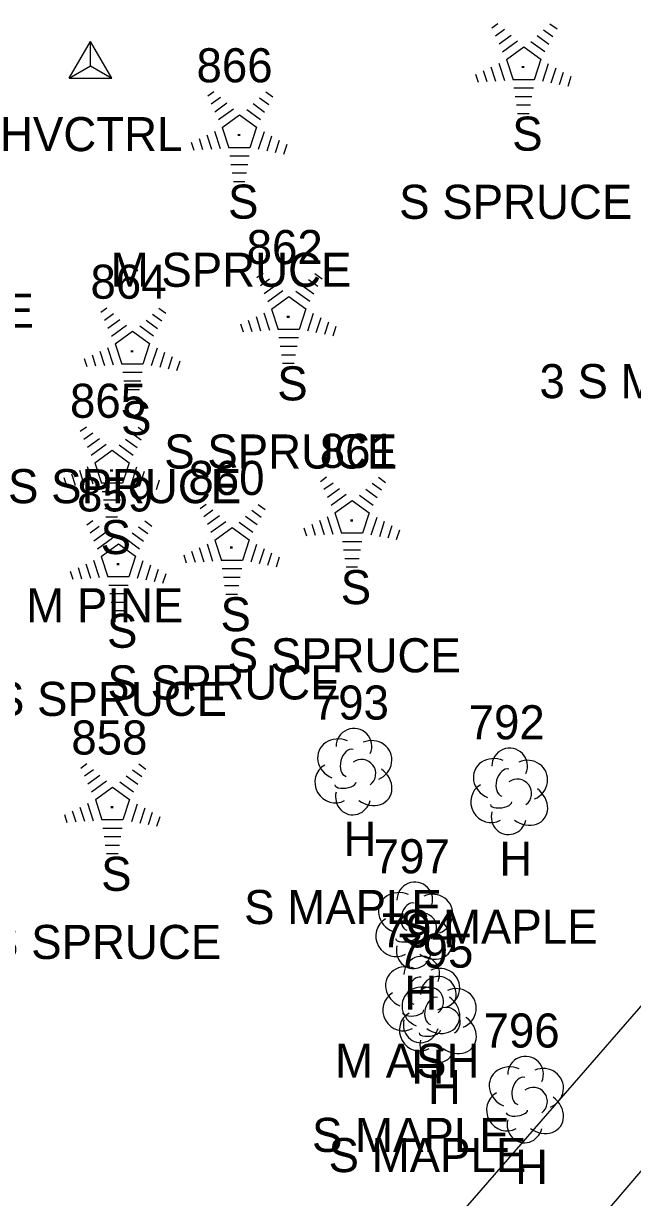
# Model space of a CAD drawing. Extents: x 1545627 to 1546562, y 571176 to 576667.
# Drawn here: x 1546211.1 to 1546246.9, y 572339.9 to 572408.8 of the extents above; entities that cross this region are included whole.
import ezdxf

# ---------------------------------------------------------------- set-up
doc = ezdxf.new("R2010")
doc.units = 0
for name, color, linetype in [('C_A', 7, 'Continuous'), ('CPSM', 7, 'Continuous'), ('L_A', 7, 'Continuous'), ('L_C', 7, 'Continuous'), ('L_I', 7, 'Continuous'), ('LAWE', 7, 'Continuous'), ('LELB', 7, 'Continuous'), ('LTC', 7, 'Continuous'), ('LTD', 7, 'Continuous')]:
    doc.layers.add(name, color=color, linetype=linetype)

msp = doc.modelspace()

# ---------------------------------------------------------------- linework, layer by layer
at = {"layer": 'CPSM'}
for p, q in [((1546213.82, 572405.561), (1546215.07, 572407.726)), ((1546216.32, 572405.561), (1546215.07, 572407.726)), ((1546215.07, 572406.282), (1546215.07, 572407.726)), ((1546213.82, 572405.561), (1546215.07, 572406.282)), ((1546215.07, 572406.282), (1546215.07, 572406.282)), ((1546215.07, 572406.282), (1546216.32, 572405.561)), ((1546213.82, 572405.561), (1546216.32, 572405.561))]:
    msp.add_line(p, q, dxfattribs=at)
at = {"layer": 'LAWE'}
msp.add_lwpolyline([(1546079.438, 571966.947), (1546077.788, 571985.488), (1546075.176, 572034.738), (1546072.514, 572073.367), (1546072.957, 572091.545), (1546079.326, 572109.636), (1546089.965, 572133.875), (1546098.205, 572146.168), (1546103.269, 572146.803), (1546106.386, 572149.622), (1546130.143, 572181.263), (1546136.759, 572192.153), (1546140.729, 572200.768), (1546161.621, 572243.317), (1546187.565, 572282.786), (1546232.645, 572334.154), (1546255.297, 572360.235), (1546268.959, 572391.116)], dxfattribs=at)
at = {"layer": 'LELB'}
msp.add_lwpolyline([(1546140.457, 572188.687), (1546144.086, 572197.302), (1546164.869, 572240.482), (1546191.763, 572281.913), (1546238.283, 572330.782), (1546258.38, 572354.309), (1546270.264, 572391.299)], dxfattribs=at)
at = {"layer": 'LTC'}
for p, q in [((1546238.614, 572408.517), (1546238.969, 572408.774)), ((1546242.013, 572408.757), (1546242.432, 572408.453)), ((1546238.824, 572408.051), (1546239.353, 572408.435)), ((1546239.033, 572407.585), (1546239.737, 572408.097)), ((1546241.27, 572408.06), (1546241.95, 572407.567)), ((1546241.641, 572408.409), (1546242.191, 572408.01)), ((1546239.243, 572407.12), (1546240.121, 572407.758)), ((1546239.468, 572406.665), (1546240.479, 572407.399)), ((1546240.479, 572407.399), (1546241.476, 572406.674)), ((1546240.899, 572407.712), (1546241.709, 572407.123)), ((1546239.468, 572406.665), (1546239.855, 572405.471)), ((1546241.476, 572406.674), (1546241.085, 572405.471)), ((1546238.102, 572406.013), (1546238.314, 572405.361)), ((1546238.558, 572406.229), (1546238.829, 572405.394)), ((1546239.013, 572406.445), (1546239.344, 572405.426)), ((1546241.914, 572406.403), (1546241.576, 572405.364)), ((1546242.358, 572406.153), (1546242.071, 572405.268)), ((1546237.647, 572405.796), (1546237.799, 572405.328)), ((1546241.085, 572405.471), (1546239.855, 572405.471)), ((1546242.803, 572405.903), (1546242.566, 572405.173)), ((1546243.247, 572405.653), (1546243.06, 572405.078)), ((1546221.948, 572404.528), (1546222.303, 572404.785)), ((1546225.347, 572404.768), (1546225.766, 572404.464)), ((1546241.047, 572404.971), (1546239.902, 572404.971)), ((1546222.158, 572404.062), (1546222.687, 572404.447)), ((1546222.368, 572403.597), (1546223.071, 572404.108)), ((1546224.605, 572404.072), (1546225.284, 572403.578)), ((1546224.975, 572404.42), (1546225.525, 572404.021)), ((1546240.963, 572404.471), (1546239.975, 572404.471)), ((1546240.879, 572403.971), (1546240.048, 572403.971)), ((1546222.577, 572403.131), (1546223.455, 572403.769)), ((1546222.802, 572402.676), (1546223.813, 572403.41)), ((1546223.813, 572403.41), (1546224.81, 572402.685)), ((1546224.233, 572403.723), (1546225.043, 572403.134)), ((1546240.795, 572403.471), (1546240.12, 572403.471)), ((1546222.802, 572402.676), (1546223.189, 572401.482)), ((1546224.81, 572402.685), (1546224.419, 572401.482)), ((1546221.436, 572402.024), (1546221.648, 572401.372)), ((1546221.892, 572402.24), (1546222.163, 572401.405)), ((1546222.347, 572402.457), (1546222.678, 572401.437)), ((1546225.248, 572402.414), (1546224.91, 572401.375)), ((1546225.693, 572402.164), (1546225.405, 572401.279)), ((1546226.137, 572401.914), (1546225.9, 572401.184)), ((1546220.981, 572401.807), (1546221.133, 572401.339)), ((1546224.419, 572401.482), (1546223.189, 572401.482)), ((1546226.581, 572401.664), (1546226.395, 572401.089)), ((1546224.381, 572400.982), (1546223.236, 572400.982)), ((1546224.297, 572400.482), (1546223.309, 572400.482)), ((1546224.213, 572399.982), (1546223.382, 572399.982)), ((1546224.13, 572399.482), (1546223.455, 572399.482)), ((1546224.835, 572393.862), (1546225.189, 572394.12)), ((1546225.044, 572393.397), (1546225.573, 572393.781)), ((1546227.862, 572393.755), (1546228.411, 572393.355)), ((1546228.233, 572394.103), (1546228.652, 572393.798)), ((1546225.254, 572392.931), (1546225.957, 572393.442)), ((1546225.463, 572392.465), (1546226.342, 572393.103)), ((1546227.12, 572393.058), (1546227.929, 572392.469)), ((1546227.491, 572393.406), (1546228.17, 572392.912)), ((1546225.688, 572392.01), (1546226.7, 572392.745)), ((1546226.7, 572392.745), (1546227.697, 572392.02)), ((1546215.673, 572391.829), (1546216.028, 572392.086)), ((1546215.883, 572391.363), (1546216.412, 572391.747)), ((1546218.7, 572391.721), (1546219.25, 572391.322)), ((1546219.071, 572392.069), (1546219.491, 572391.765)), ((1546224.778, 572391.575), (1546225.049, 572390.74)), ((1546225.233, 572391.791), (1546225.564, 572390.772)), ((1546225.688, 572392.01), (1546226.075, 572390.817)), ((1546227.697, 572392.02), (1546227.305, 572390.817)), ((1546228.134, 572391.749), (1546227.796, 572390.71)), ((1546228.579, 572391.499), (1546228.291, 572390.614)), ((1546216.092, 572390.897), (1546216.796, 572391.409)), ((1546216.302, 572390.432), (1546217.18, 572391.07)), ((1546217.958, 572391.024), (1546218.768, 572390.435)), ((1546218.329, 572391.372), (1546219.009, 572390.879)), ((1546223.867, 572391.142), (1546224.019, 572390.674)), ((1546224.322, 572391.358), (1546224.534, 572390.707)), ((1546227.305, 572390.817), (1546226.075, 572390.817)), ((1546229.023, 572391.249), (1546228.786, 572390.519)), ((1546229.467, 572390.998), (1546229.281, 572390.424)), ((1546216.527, 572389.977), (1546217.538, 572390.711)), ((1546217.538, 572390.711), (1546218.535, 572389.986)), ((1546227.267, 572390.317), (1546226.122, 572390.317)), ((1546215.617, 572389.541), (1546215.888, 572388.706)), ((1546216.072, 572389.757), (1546216.403, 572388.738)), ((1546216.527, 572389.977), (1546216.914, 572388.783)), ((1546218.535, 572389.986), (1546218.144, 572388.783)), ((1546218.973, 572389.715), (1546218.635, 572388.676)), ((1546219.417, 572389.465), (1546219.13, 572388.58)), ((1546227.183, 572389.817), (1546226.195, 572389.817)), ((1546214.706, 572389.108), (1546214.858, 572388.64)), ((1546215.161, 572389.325), (1546215.373, 572388.673)), ((1546218.144, 572388.783), (1546216.914, 572388.783)), ((1546219.862, 572389.215), (1546219.625, 572388.485)), ((1546220.306, 572388.965), (1546220.119, 572388.39)), ((1546227.1, 572389.317), (1546226.268, 572389.317)), ((1546227.016, 572388.817), (1546226.341, 572388.817)), ((1546218.106, 572388.283), (1546216.961, 572388.283)), ((1546218.022, 572387.783), (1546217.034, 572387.783)), ((1546217.938, 572387.283), (1546217.106, 572387.283)), ((1546217.854, 572386.783), (1546217.179, 572386.783)), ((1546214.473, 572384.841), (1546214.828, 572385.099)), ((1546214.683, 572384.376), (1546215.212, 572384.76)), ((1546217.501, 572384.733), (1546218.05, 572384.334)), ((1546217.872, 572385.082), (1546218.291, 572384.777)), ((1546214.893, 572383.91), (1546215.596, 572384.421)), ((1546215.102, 572383.444), (1546215.981, 572384.082)), ((1546216.758, 572384.037), (1546217.568, 572383.448)), ((1546217.13, 572384.385), (1546217.809, 572383.891)), ((1546215.327, 572382.989), (1546216.338, 572383.724)), ((1546216.338, 572383.724), (1546217.336, 572382.999)), ((1546214.417, 572382.554), (1546214.688, 572381.718)), ((1546214.872, 572382.77), (1546215.203, 572381.751)), ((1546215.327, 572382.989), (1546215.714, 572381.796)), ((1546217.336, 572382.999), (1546216.944, 572381.796)), ((1546217.773, 572382.728), (1546217.435, 572381.688)), ((1546213.506, 572382.12), (1546213.658, 572381.653)), ((1546213.961, 572382.337), (1546214.173, 572381.685)), ((1546218.218, 572382.478), (1546217.93, 572381.593)), ((1546218.662, 572382.228), (1546218.425, 572381.498)), ((1546219.106, 572381.977), (1546218.92, 572381.403)), ((1546228.556, 572381.903), (1546228.911, 572382.161)), ((1546231.955, 572382.144), (1546232.374, 572381.839)), ((1546216.944, 572381.796), (1546215.714, 572381.796)), ((1546216.906, 572381.296), (1546215.761, 572381.296)), ((1546228.766, 572381.438), (1546229.295, 572381.822)), ((1546228.975, 572380.972), (1546229.679, 572381.483)), ((1546231.213, 572381.447), (1546231.892, 572380.953)), ((1546231.583, 572381.795), (1546232.133, 572381.396)), ((1546216.822, 572380.796), (1546215.834, 572380.796)), ((1546221.506, 572380.312), (1546221.86, 572380.569)), ((1546224.904, 572380.552), (1546225.323, 572380.248)), ((1546229.185, 572380.506), (1546230.063, 572381.144)), ((1546229.41, 572380.051), (1546230.421, 572380.786)), ((1546230.421, 572380.786), (1546231.418, 572380.061)), ((1546230.841, 572381.099), (1546231.651, 572380.51)), ((1546216.738, 572380.296), (1546215.907, 572380.296)), ((1546216.655, 572379.796), (1546215.98, 572379.796)), ((1546221.715, 572379.846), (1546222.245, 572380.231)), ((1546221.925, 572379.381), (1546222.629, 572379.892)), ((1546224.162, 572379.856), (1546224.841, 572379.362)), ((1546224.533, 572380.204), (1546225.082, 572379.805)), ((1546228.955, 572379.832), (1546229.286, 572378.813)), ((1546229.41, 572380.051), (1546229.797, 572378.858)), ((1546231.418, 572380.061), (1546231.027, 572378.858)), ((1546231.856, 572379.79), (1546231.518, 572378.75)), ((1546214.851, 572379.345), (1546215.205, 572379.603)), ((1546215.06, 572378.88), (1546215.589, 572379.264)), ((1546217.878, 572379.238), (1546218.427, 572378.838)), ((1546218.249, 572379.586), (1546218.668, 572379.281)), ((1546222.135, 572378.915), (1546223.013, 572379.553)), ((1546222.359, 572378.46), (1546223.371, 572379.194)), ((1546223.371, 572379.194), (1546224.368, 572378.469)), ((1546223.791, 572379.507), (1546224.6, 572378.918)), ((1546227.589, 572379.182), (1546227.741, 572378.715)), ((1546228.044, 572379.399), (1546228.256, 572378.747)), ((1546228.5, 572379.616), (1546228.771, 572378.78)), ((1546232.3, 572379.54), (1546232.013, 572378.655)), ((1546232.745, 572379.29), (1546232.508, 572378.56)), ((1546215.27, 572378.414), (1546215.974, 572378.925)), ((1546215.479, 572377.948), (1546216.358, 572378.586)), ((1546217.136, 572378.541), (1546217.945, 572377.952)), ((1546217.507, 572378.889), (1546218.186, 572378.395)), ((1546222.359, 572378.46), (1546222.746, 572377.266)), ((1546224.368, 572378.469), (1546223.977, 572377.266)), ((1546231.027, 572378.858), (1546229.797, 572378.858)), ((1546233.189, 572379.039), (1546233.003, 572378.465)), ((1546215.704, 572377.493), (1546216.716, 572378.228)), ((1546216.716, 572378.228), (1546217.713, 572377.503)), ((1546220.994, 572377.808), (1546221.205, 572377.156)), ((1546221.449, 572378.024), (1546221.72, 572377.189)), ((1546221.905, 572378.241), (1546222.235, 572377.221)), ((1546224.805, 572378.198), (1546224.467, 572377.159)), ((1546225.25, 572377.948), (1546224.962, 572377.064)), ((1546230.989, 572378.358), (1546229.844, 572378.358)), ((1546230.905, 572377.858), (1546229.917, 572377.858)), ((1546214.794, 572377.058), (1546215.065, 572376.223)), ((1546215.249, 572377.274), (1546215.58, 572376.255)), ((1546215.704, 572377.493), (1546216.091, 572376.3)), ((1546217.713, 572377.503), (1546217.321, 572376.3)), ((1546218.15, 572377.232), (1546217.812, 572376.193)), ((1546220.538, 572377.591), (1546220.69, 572377.123)), ((1546223.977, 572377.266), (1546222.746, 572377.266)), ((1546225.695, 572377.698), (1546225.457, 572376.969)), ((1546226.139, 572377.448), (1546225.952, 572376.874)), ((1546230.821, 572377.358), (1546229.99, 572377.358)), ((1546213.883, 572376.625), (1546214.035, 572376.157)), ((1546214.339, 572376.841), (1546214.55, 572376.19)), ((1546218.595, 572376.982), (1546218.307, 572376.097)), ((1546219.039, 572376.732), (1546218.802, 572376.002)), ((1546219.484, 572376.481), (1546219.297, 572375.907)), ((1546223.938, 572376.766), (1546222.794, 572376.766)), ((1546230.738, 572376.858), (1546230.063, 572376.858)), ((1546217.321, 572376.3), (1546216.091, 572376.3)), ((1546217.283, 572375.8), (1546216.139, 572375.8)), ((1546223.855, 572376.266), (1546222.866, 572376.266)), ((1546223.771, 572375.766), (1546222.939, 572375.766)), ((1546217.199, 572375.3), (1546216.211, 572375.3)), ((1546223.687, 572375.266), (1546223.012, 572375.266)), ((1546217.116, 572374.8), (1546216.284, 572374.8)), ((1546217.032, 572374.3), (1546216.357, 572374.3)), ((1546214.505, 572365.08), (1546214.859, 572365.337)), ((1546217.903, 572365.32), (1546218.322, 572365.016)), ((1546214.714, 572364.614), (1546215.244, 572364.998)), ((1546214.924, 572364.148), (1546215.628, 572364.66)), ((1546217.532, 572364.972), (1546218.082, 572364.573)), ((1546215.134, 572363.683), (1546216.012, 572364.321)), ((1546215.358, 572363.228), (1546216.37, 572363.962)), ((1546216.37, 572363.962), (1546217.367, 572363.237)), ((1546216.79, 572364.275), (1546217.599, 572363.686)), ((1546217.161, 572364.623), (1546217.84, 572364.13)), ((1546213.993, 572362.576), (1546214.204, 572361.924)), ((1546214.448, 572362.792), (1546214.719, 572361.957)), ((1546214.904, 572363.008), (1546215.234, 572361.989)), ((1546215.358, 572363.228), (1546215.745, 572362.034)), ((1546217.367, 572363.237), (1546216.976, 572362.034)), ((1546217.804, 572362.966), (1546217.467, 572361.927)), ((1546218.249, 572362.716), (1546217.962, 572361.831)), ((1546213.537, 572362.359), (1546213.689, 572361.891)), ((1546216.976, 572362.034), (1546215.745, 572362.034)), ((1546218.694, 572362.466), (1546218.457, 572361.736)), ((1546219.138, 572362.216), (1546218.951, 572361.641)), ((1546216.937, 572361.534), (1546215.793, 572361.534)), ((1546216.854, 572361.034), (1546215.865, 572361.034)), ((1546216.77, 572360.534), (1546215.938, 572360.534)), ((1546216.686, 572360.034), (1546216.011, 572360.034))]:
    msp.add_line(p, q, dxfattribs=at)
at = {"layer": 'LTD'}
for p, q in [((1546230.476, 572364.922), (1546230.476, 572364.922)), ((1546230.476, 572364.922), (1546230.476, 572364.922)), ((1546239.612, 572363.765), (1546239.612, 572363.765)), ((1546239.612, 572363.765), (1546239.612, 572363.765)), ((1546234.045, 572355.902), (1546234.045, 572355.902)), ((1546234.045, 572355.902), (1546234.045, 572355.902)), ((1546234.456, 572351.55), (1546234.456, 572351.55)), ((1546234.456, 572351.55), (1546234.456, 572351.55)), ((1546235.428, 572350.364), (1546235.428, 572350.364)), ((1546235.428, 572350.364), (1546235.428, 572350.364)), ((1546240.541, 572345.675), (1546240.541, 572345.675)), ((1546240.541, 572345.675), (1546240.541, 572345.675))]:
    msp.add_line(p, q, dxfattribs=at)
for centre in [(1546230.523, 572366.356), (1546239.658, 572365.199), (1546234.092, 572357.336), (1546234.503, 572352.984), (1546235.474, 572351.798), (1546240.588, 572347.109)]:
    msp.add_arc(centre, 1.047, 335.52715, 180.95627, dxfattribs=at)
for centre, major_axis, ratio, start_param, end_param in [((1546229.684, 572365.588), (1.21, -0.512), 0.895232, 1.570796, 4.712389), ((1546231.517, 572365.505), (-1.141, -0.483), 0.949671, 1.570796, 4.712389), ((1546230.267, 572365.38), (-0.208, -0.792), 0.645439, 3.141593, 6.283185), ((1546230.976, 572364.755), (-0.5, 0.667), 0.989748, 3.141593, 6.283185), ((1546238.82, 572364.432), (1.21, -0.512), 0.895232, 1.570796, 4.712389), ((1546240.653, 572364.349), (-1.141, -0.483), 0.949671, 1.570796, 4.712389), ((1546229.393, 572364.213), (0.584, -1.042), 0.959034, 3.141593, 6.283185), ((1546231.476, 572364.089), (-1.09, 0.792), 0.841452, 1.570796, 4.712389), ((1546239.403, 572364.223), (-0.208, -0.792), 0.645439, 3.141593, 6.283185), ((1546230.018, 572364.172), (-0.625, -0.083), 0.423636, 0, 3.141593), ((1546238.529, 572363.057), (0.584, -1.042), 0.959034, 3.141593, 6.283185), ((1546240.112, 572363.599), (-0.5, 0.667), 0.989748, 3.141593, 6.283185), ((1546230.476, 572363.422), (0.265, 1.061), 0.942809, 1.570796, 4.712389), ((1546240.612, 572362.932), (-1.09, 0.792), 0.841452, 1.570796, 4.712389), ((1546239.154, 572363.015), (-0.625, -0.083), 0.423636, 0, 3.141593), ((1546239.612, 572362.265), (0.265, 1.061), 0.942809, 1.570796, 4.712389), ((1546233.254, 572356.568), (1.21, -0.512), 0.895232, 1.570796, 4.712389), ((1546235.087, 572356.485), (-1.141, -0.483), 0.949671, 1.570796, 4.712389), ((1546233.837, 572356.36), (-0.208, -0.792), 0.645439, 3.141593, 6.283185), ((1546234.545, 572355.735), (-0.5, 0.667), 0.989748, 3.141593, 6.283185), ((1546232.962, 572355.193), (0.584, -1.042), 0.959034, 3.141593, 6.283185), ((1546235.045, 572355.069), (-1.09, 0.792), 0.841452, 1.570796, 4.712389), ((1546233.587, 572355.152), (-0.625, -0.083), 0.423636, 0, 3.141593), ((1546234.046, 572354.402), (0.265, 1.061), 0.942809, 1.570796, 4.712389), ((1546233.664, 572352.216), (1.21, -0.512), 0.895232, 1.570796, 4.712389), ((1546235.498, 572352.133), (-1.141, -0.483), 0.949671, 1.570796, 4.712389), ((1546234.636, 572351.031), (1.21, -0.512), 0.895232, 1.570796, 4.712389), ((1546234.248, 572352.008), (-0.208, -0.792), 0.645439, 3.141593, 6.283185), ((1546234.956, 572351.383), (-0.5, 0.667), 0.989748, 3.141593, 6.283185), ((1546236.469, 572350.948), (-1.141, -0.483), 0.949671, 1.570796, 4.712389), ((1546233.373, 572350.841), (0.584, -1.042), 0.959034, 3.141593, 6.283185), ((1546235.219, 572350.822), (-0.208, -0.792), 0.645439, 3.141593, 6.283185), ((1546235.456, 572350.717), (-1.09, 0.792), 0.841452, 1.570796, 4.712389), ((1546233.998, 572350.8), (-0.625, -0.083), 0.423636, 0, 3.141593), ((1546235.928, 572350.197), (-0.5, 0.667), 0.989748, 3.141593, 6.283185), ((1546234.344, 572349.656), (0.584, -1.042), 0.959034, 3.141593, 6.283185), ((1546234.456, 572350.05), (0.265, 1.061), 0.942809, 1.570796, 4.712389), ((1546236.428, 572349.531), (-1.09, 0.792), 0.841452, 1.570796, 4.712389), ((1546234.969, 572349.614), (-0.625, -0.083), 0.423636, 0, 3.141593), ((1546235.428, 572348.864), (0.265, 1.061), 0.942809, 1.570796, 4.712389), ((1546239.749, 572346.342), (1.21, -0.512), 0.895232, 1.570796, 4.712389), ((1546241.583, 572346.259), (-1.141, -0.483), 0.949671, 1.570796, 4.712389), ((1546240.333, 572346.133), (-0.208, -0.792), 0.645439, 3.141593, 6.283185), ((1546241.041, 572345.508), (-0.5, 0.667), 0.989748, 3.141593, 6.283185), ((1546239.458, 572344.967), (0.584, -1.042), 0.959034, 3.141593, 6.283185), ((1546241.541, 572344.842), (-1.09, 0.792), 0.841452, 1.570796, 4.712389), ((1546240.083, 572344.925), (-0.625, -0.083), 0.423636, 0, 3.141593), ((1546240.542, 572344.175), (0.265, 1.061), 0.942809, 1.570796, 4.712389)]:
    msp.add_ellipse(centre, major_axis=major_axis, ratio=ratio, start_param=start_param, end_param=end_param, dxfattribs=at)

# ---------------------------------------------------------------- texts
at = {"layer": 'C_A'}
msp.add_text('HVCTRL', height=2, dxfattribs=at).set_placement((1546209.763, 572401.282))
at = {"layer": 'L_A'}
for s, p in [('S', (1546239.805, 572401.309)), ('S', (1546223.139, 572397.32)), ('S', (1546226.025, 572386.654)), ('S', (1546216.864, 572384.621)), ('S', (1546215.664, 572377.633)), ('S', (1546229.747, 572374.695)), ('S', (1546222.696, 572373.104)), ('S', (1546216.041, 572372.137)), ('H', (1546229.909, 572359.922)), ('H', (1546239.045, 572358.765)), ('S', (1546215.696, 572357.872)), ('H', (1546233.478, 572350.902)), ('H', (1546233.889, 572346.55)), ('H', (1546234.861, 572345.364)), ('H', (1546239.974, 572340.675))]:
    msp.add_text(s, height=2, dxfattribs=at).set_placement(p)
at = {"layer": 'L_C'}
for s, p in [('S SPRUCE', (1546233.175, 572397.309)), ('M SPRUCE', (1546216.257, 572393.32)), ('S SPRUCE', (1546198.08, 572390.92)), ('3 S MAPLES', (1546241.406, 572386.785)), ('S SPRUCE', (1546219.395, 572382.654)), ('S SPRUCE', (1546210.234, 572380.621)), ('M PINE', (1546211.302, 572373.633)), ('S SPRUCE', (1546223.117, 572370.695)), ('S SPRUCE', (1546216.067, 572369.104)), ('S SPRUCE', (1546209.411, 572368.137)), ('S MAPLE', (1546224.082, 572355.922)), ('S MAPLE', (1546233.218, 572354.765)), ('S SPRUCE', (1546209.066, 572353.872)), ('M ASH', (1546229.415, 572346.902)), ('S MAPLE', (1546228.062, 572342.55)), ('S MAPLE', (1546229.034, 572341.364))]:
    msp.add_text(s, height=2, dxfattribs=at).set_placement(p)
at = {"layer": 'L_I'}
for s, p in [('866', (1546221.289, 572405.32)), ('862', (1546224.23, 572394.654)), ('864', (1546215.069, 572392.621)), ('865', (1546213.869, 572385.633)), ('861', (1546228.519, 572382.695)), ('860', (1546220.815, 572381.104)), ('859', (1546214.285, 572380.137)), ('793', (1546228.114, 572367.922)), ('792', (1546237.25, 572366.765)), ('858', (1546213.948, 572365.872)), ('797', (1546231.683, 572358.902)), ('794', (1546232.094, 572354.55)), ('795', (1546233.065, 572353.364)), ('796', (1546238.124, 572348.675))]:
    msp.add_text(s, height=2, dxfattribs=at).set_placement(p)
at = {"layer": 'LTC'}
for p in [(1546240.362, 572406.413), (1546223.696, 572402.424), (1546226.582, 572391.758), (1546217.421, 572389.725), (1546216.221, 572382.737), (1546230.304, 572379.799), (1546223.253, 572378.208), (1546216.598, 572377.241), (1546216.252, 572362.976)]:
    msp.add_text('.', height=1.037, rotation=270, dxfattribs=at).set_placement(p)

doc.saveas('drawing.dxf')
